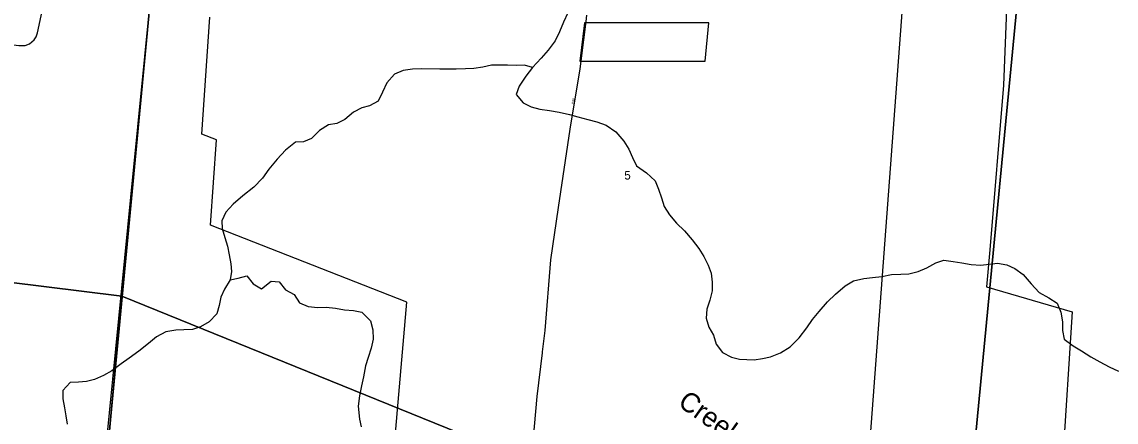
# Model space of a CAD drawing. Extents: x 1312308 to 1684953, y 460642 to 865172.
# Drawn here: x 1486286 to 1493271, y 587867 to 590421 of the extents above; entities that cross this region are included whole.
import ezdxf

# ---------------------------------------------------------------- set-up
doc = ezdxf.new("R2010")
doc.units = 0
for name, color, linetype in [('GM_X_City_Street', 7, 'Continuous'), ('GM_X_City_Street_Text', 7, 'Continuous'), ('GM_X_Corporation', 7, 'Continuous'), ('GM_X_County_Road', 7, 'Continuous'), ('GM_X_Minor_River', 7, 'Continuous'), ('GM_X_Minor_River_Text', 7, 'Continuous'), ('GM_X_Section', 7, 'Continuous'), ('GM_X_Section_Text', 7, 'Continuous'), ('GM_X_Township', 7, 'Continuous'), ('GM_X_Township_Road', 7, 'Continuous'), ('GM_X_Township_ROW', 7, 'Continuous'), ('GM_X_Township_Subdivision', 7, 'Continuous')]:
    doc.layers.add(name, color=color, linetype=linetype)

msp = doc.modelspace()

# ---------------------------------------------------------------- linework, layer by layer
at = {"layer": 'GM_X_City_Street'}
for points in [[(1489609.1, 588316.4), (1489625.4, 588451.1), (1489662.7, 588903.6), (1489711.7, 589237.5), (1489786, 589737.4), (1489850, 590121.2), (1489873.5, 590306.6), (1489873.6, 590307.4)], [(1489481.1, 587000.7), (1489524.8, 587456.4), (1489574.6, 588031), (1489608.2, 588309.3), (1489609.1, 588316.4)]]:
    msp.add_lwpolyline(points, dxfattribs=at)
at = {"layer": 'GM_X_Corporation'}
for points in [[(1492597.1, 591146.5), (1492552.3, 590017.6), (1492465.8, 588967.2), (1492443.9, 588731.6), (1492991, 588570.3), (1492929.4, 587608.6)], [(1488640.9, 587455), (1488744.1, 588633.8), (1487489.2, 589124.4), (1487527.3, 589668.6), (1487433.9, 589704.4), (1487486.3, 590452.4)]]:
    msp.add_lwpolyline(points, dxfattribs=at)
msp.add_lwpolyline([(1489848.3, 590170.5), (1490648.3, 590170.4), (1490670.7, 590415.4), (1489877.1, 590415.5)], close=True, dxfattribs=at)
at = {"layer": 'GM_X_County_Road'}
msp.add_lwpolyline([(1489873.6, 590307.4), (1489888.3, 590423.2), (1489892.5, 590464.9)], dxfattribs=at)
at = {"layer": 'GM_X_Minor_River'}
for points in [[(1489770.1, 590479), (1489744.2, 590419.6), (1489718.1, 590358.2), (1489690.2, 590300.8), (1489646.2, 590242), (1489600.3, 590189.2), (1489546.3, 590130.7), (1489502.4, 590075.8), (1489460.2, 590010.9), (1489440.4, 589957.3), (1489485, 589905.8), (1489536.5, 589880.1), (1489592.2, 589864.3), (1489654.3, 589856.3), (1489716.2, 589844.4), (1489782.1, 589830.3), (1489833.9, 589816.6), (1489897.6, 589798.6), (1489955.4, 589784.7), (1490015, 589762.8), (1490078, 589720.7), (1490128.4, 589660.9), (1490161, 589609.7), (1490183.4, 589556.8), (1490209.9, 589503.8), (1490272.8, 589457.7), (1490327.5, 589407.8), (1490349.9, 589354.9), (1490368.3, 589298.1), (1490386.7, 589243.4), (1490419.2, 589190.2), (1490463.7, 589136.6), (1490516.5, 589088.8), (1490564.9, 589031.1), (1490607.4, 588975.5), (1490639.9, 588924.3), (1490666.4, 588869.3), (1490684.9, 588818.6), (1490693.1, 588760.1), (1490693.4, 588705.9), (1490677.5, 588646.2), (1490657.6, 588588.6), (1490653.8, 588530.5), (1490670.1, 588473.8), (1490700.6, 588422.7), (1490718.9, 588363.9), (1490757.4, 588310.5), (1490814.8, 588282.6), (1490866.7, 588268.9), (1490960.9, 588264), (1491013.4, 588272.4), (1491064.1, 588284.8), (1491129.1, 588308.9), (1491190.6, 588347.1), (1491248.7, 588405.5), (1491296.8, 588468.3), (1491332.7, 588521.3), (1491374.4, 588572.2), (1491428.6, 588634.8), (1491480.4, 588683.3), (1491542.4, 588737.6), (1491595.5, 588768.1), (1491660.3, 588784.1), (1491716.8, 588790.4), (1491775.3, 588796.6), (1491837.9, 588808.7), (1491896.3, 588810.9), (1491948.6, 588813.2), (1492007.4, 588829.5), (1492062.3, 588851.8), (1492119.6, 588884.2), (1492170.4, 588900.7), (1492230.4, 588892.8), (1492286.4, 588883)], [(1489546.3, 590130.7), (1489494.5, 590146.3), (1489444.2, 590143.9), (1489386, 590145.7), (1489333.7, 590145.3), (1489283.5, 590144.9), (1489228.9, 590132.5), (1489170.3, 590124.3), (1489118, 590121.9), (1489057.7, 590119.8), (1489007.4, 590119.4), (1488953.2, 590119), (1488836.7, 590122.7), (1488780.4, 590120.4), (1488719.9, 590112.3), (1488664.8, 590087.9), (1488614.9, 590033.2), (1488586.9, 589973.9), (1488561, 589914.5), (1488505.8, 589886.1), (1488455.2, 589873.6), (1488402.1, 589845.2), (1488346.4, 589798.7), (1488295.3, 589772.2), (1488242.8, 589763.8), (1488185.4, 589727.4), (1488135.6, 589676.8), (1488082.7, 589656.4), (1488032.4, 589653.9), (1487968.6, 589603.7), (1487914.5, 589545.2), (1487862.3, 589482.6), (1487822.3, 589423.6), (1487766.3, 589367.2), (1487696.2, 589311.1), (1487634.3, 589258.8), (1487588.5, 589208.1), (1487562.7, 589152.7), (1487565.2, 589102.4), (1487581.5, 589045.7), (1487597.8, 588991), (1487608.1, 588934.5), (1487620.4, 588877.9), (1487622.9, 588827.7), (1487615.2, 588775.7), (1487579.2, 588716.6), (1487555.5, 588665.2), (1487545.8, 588611.3), (1487530.1, 588557.5), (1487482.3, 588506.8), (1487427, 588474.4), (1487374.3, 588458), (1487319.9, 588455.7), (1487269.6, 588453.2), (1487205, 588443.2), (1487145.7, 588410.9), (1487094.2, 588368.4), (1487032.4, 588320.1), (1486970.7, 588275.9), (1486919.4, 588239.3), (1486859.7, 588195), (1486806.5, 588164.6), (1486749.4, 588138.2), (1486698.8, 588125.8), (1486646.4, 588121.4), (1486594.2, 588121), (1486546.3, 588068.3), (1486546.7, 588016.1), (1486558.9, 587957.5), (1486567.4, 587907), (1486575.8, 587854.6)], [(1492286.4, 588883), (1492346.3, 588873.1), (1492406.5, 588869.2), (1492460.9, 588875.5), (1492513.4, 588881.9), (1492573.3, 588872), (1492624.9, 588848.3), (1492677.9, 588808.5), (1492728.3, 588750.8), (1492780.8, 588694.9), (1492842.1, 588660.9), (1492895.3, 588627.1), (1492917.5, 588568.2), (1492927.7, 588507.7), (1492928, 588451.5), (1492940.3, 588396.9), (1492997.3, 588354.9), (1493050.5, 588321.2), (1493109.6, 588283.2), (1493166.9, 588251.3), (1493226.1, 588219.3), (1493285.5, 588191.4)], [(1487615.2, 588775.7), (1487665.8, 588786.2), (1487722.5, 588800.5), (1487763.1, 588749), (1487816.4, 588717.3), (1487878.2, 588767.5), (1487928.3, 588761.9), (1487968.9, 588710.5), (1488024.2, 588680.7), (1488058.8, 588629.4), (1488114.3, 588605.6), (1488174.3, 588597.7), (1488228.6, 588600), (1488288.7, 588594.2), (1488344.7, 588584.4), (1488402.8, 588580.6), (1488456.7, 588568.9), (1488511.2, 588513), (1488525.6, 588456.3), (1488527.7, 588396), (1488515.8, 588338.2), (1488495.9, 588278.6), (1488480.2, 588226.9), (1488466, 588157.1), (1488454.1, 588099.2), (1488442.1, 588035.4), (1488432, 587969.5), (1488441.5, 587886.9), (1488452, 587836.3)]]:
    msp.add_lwpolyline(points, dxfattribs=at)
at = {"layer": 'GM_X_Section'}
for points in [[(1482090.2, 594892.5), (1487448.9, 594128), (1486924.7, 588670.8), (1481512.2, 589340.2)], [(1487448.9, 594128), (1492765.2, 591848.7), (1492253.1, 586509.3), (1486924.7, 588670.8)], [(1492765.2, 591848.7), (1498166, 591951.3), (1497694, 586401.3), (1492253.1, 586509.3)], [(1481512.2, 589340.2), (1486924.7, 588670.8), (1486417.3, 583147.3), (1481083.5, 583853.2)], [(1486924.7, 588670.8), (1492253.1, 586509.3), (1491791, 581160.9), (1486417.3, 583147.3)]]:
    msp.add_lwpolyline(points, close=True, dxfattribs=at)
at = {"layer": 'GM_X_Township'}
for points in [[(1488668.8, 607582.4), (1488397.9, 604604.1), (1488382.5, 604434.9), (1488301.6, 603539.3), (1488222.7, 602672.8), (1488060.1, 600883), (1487942, 599584.2), (1487890.5, 599026.4), (1487873.4, 598830.3), (1487853.3, 598605.4), (1487694.3, 596830.2), (1487177.2, 591380.6), (1487128.9, 590797.4), (1486724.4, 586538.1), (1486296.6, 581644.3)], [(1486296.6, 581644.3), (1486724.4, 586538.1), (1487128.9, 590797.4), (1487177.2, 591380.6), (1487694.3, 596830.2), (1487853.3, 598605.4), (1487873.4, 598830.3), (1487890.5, 599026.4), (1487942, 599584.2), (1488060.1, 600883), (1488222.7, 602672.8), (1488301.6, 603539.3), (1488382.5, 604434.9), (1488397.9, 604604.1), (1488668.8, 607582.4)]]:
    msp.add_lwpolyline(points, dxfattribs=at)
at = {"layer": 'GM_X_Township_Road'}
for points in [[(1486981.2, 589302), (1487114.6, 590652.6)], [(1486752, 586808), (1486751.7, 586826), (1486749.6, 586957.7), (1486981.2, 589302)]]:
    msp.add_lwpolyline(points, dxfattribs=at)
at = {"layer": 'GM_X_Township_ROW'}
msp.add_lwpolyline([(1491207.9, 581151.1), (1491188, 582238.2), (1491338, 582760.4), (1491357.3, 583148.7), (1491425, 584055.3), (1492028.9, 592132.8)], dxfattribs=at)
at = {"layer": 'GM_X_Township_Subdivision'}
msp.add_lwpolyline([(1485659.9, 591408.3), (1485634.2, 591124.6), (1485585, 590844.9), (1485507, 590476.1), (1485514.4, 590430), (1485561.4, 590380.2), (1485617.6, 590355.2), (1485720.9, 590338.6), (1485786, 590329.9), (1485878.6, 590317.5), (1486072.2, 590294.6), (1486121.2, 590288.8), (1486267.4, 590269.9), (1486295.1, 590269.9), (1486307.4, 590271.6), (1486334.2, 590280.5), (1486364.6, 590307.3), (1486377.5, 590326.7), (1486385.8, 590352.5), (1486469.5, 590738.5), (1486501, 591010.4), (1486546.3, 591303.9), (1486559.8, 591467.4)], dxfattribs=at)

# ---------------------------------------------------------------- texts
at = {"layer": 'GM_X_City_Street_Text'}
msp.add_text('PIKE', height=12.5, rotation=80.83576, dxfattribs=at).set_placement((1489807.7, 589897.6))
at = {"layer": 'GM_X_Minor_River_Text'}
msp.add_text('Creek', height=125, rotation=324.70178, dxfattribs=at).set_placement((1490466.5, 587976.1))
at = {"layer": 'GM_X_Section_Text'}
msp.add_text('5', height=55.3, rotation=0.00001, dxfattribs=at).set_placement((1490131.5, 589415.2))

doc.saveas('drawing.dxf')
